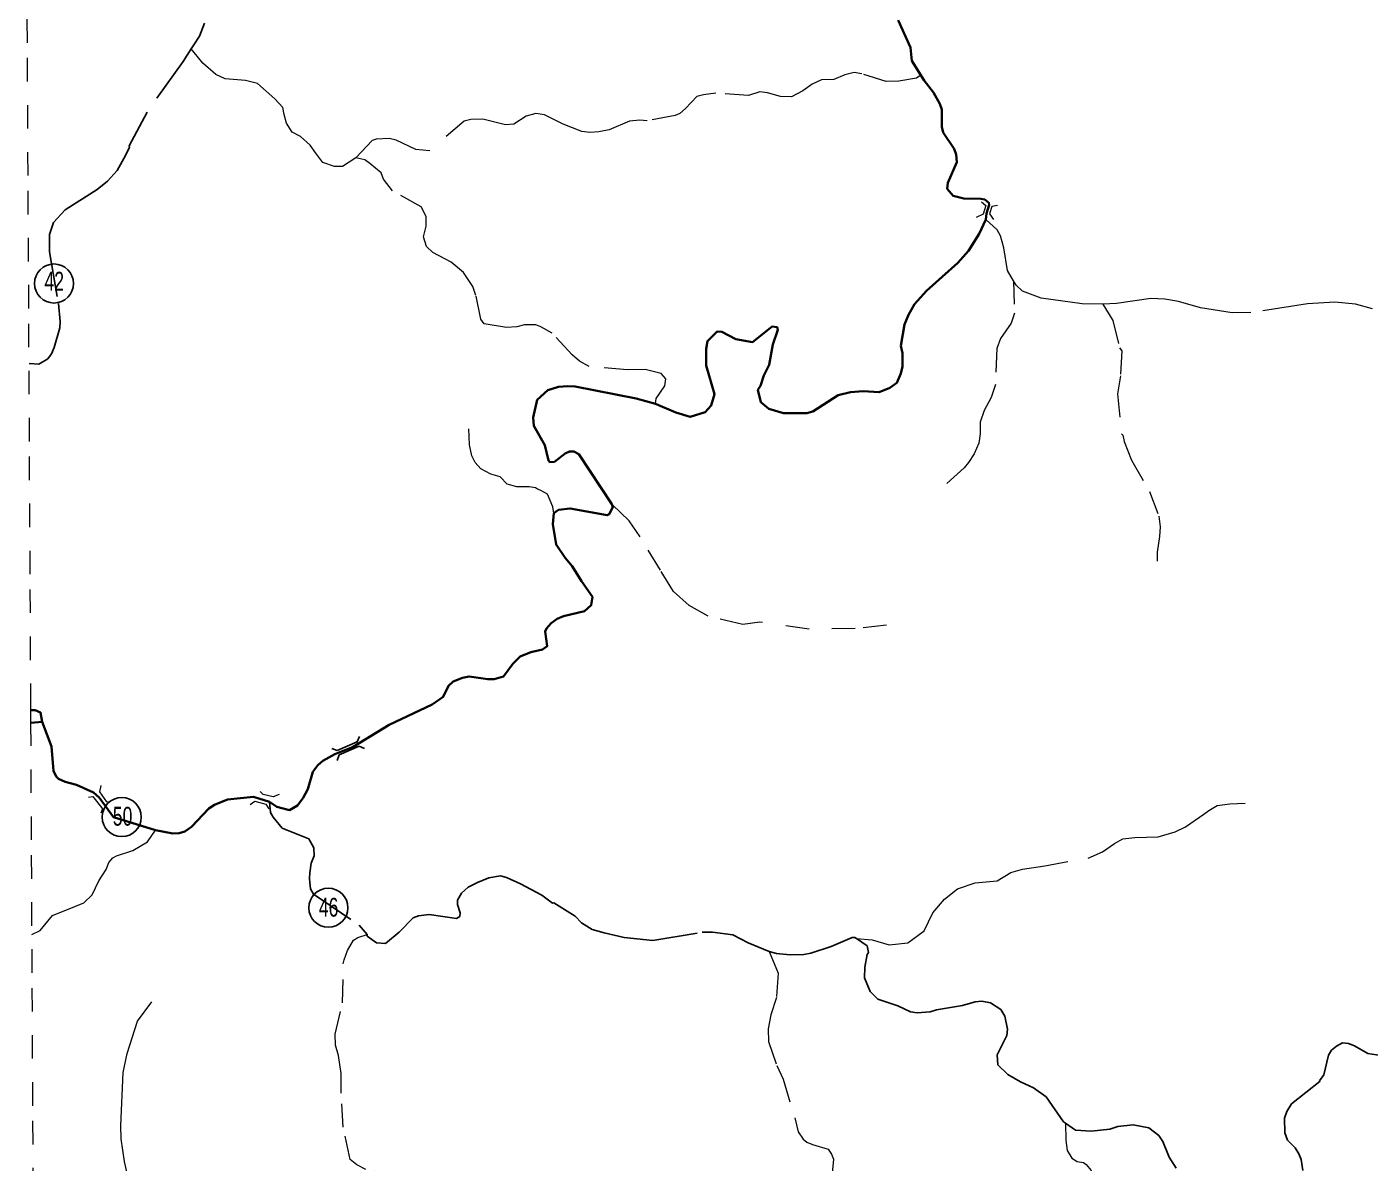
# Model space of a CAD drawing. Extents: x 423 to 448.8, y 7456.3 to 7484.
# Drawn here: x 423.01 to 428.72, y 7474.65 to 7479.48 of the extents above; entities that cross this region are included whole.
import ezdxf
from ezdxf.enums import TextEntityAlignment as Align

# ---------------------------------------------------------------- set-up
doc = ezdxf.new("R2010")
doc.units = 0
doc.header["$LTSCALE"] = 0.032
for name, pattern in [('LONG_DASHED', [7.5, 6, -1.5]), ('MEDIUM_DASHED', [4.5, 3, -1.5]), ('SHORT_DASHED', [2.7, 1.5, -1.2])]:
    doc.linetypes.add(name, pattern=pattern)
for name, color, linetype, lineweight in [('10', 7, 'Continuous', 25), ('11', 7, 'Continuous', 13), ('13', 7, 'Continuous', 25), ('2', 7, 'Continuous', 35), ('35', 7, 'SHORT_DASHED', 13), ('4', 7, 'LONG_DASHED', 25), ('5', 7, 'LONG_DASHED', 13), ('6', 7, 'MEDIUM_DASHED', 13), ('7', 7, 'Continuous', 13)]:
    doc.layers.add(name, color=color, linetype=linetype, lineweight=lineweight)
doc.layers.add('61', color=7, linetype='Continuous')

msp = doc.modelspace()

# ---------------------------------------------------------------- linework, layer by layer
at = {"layer": '10'}
for p, q in [((424.3335, 7476.3992), (424.3104, 7476.4085)), ((424.3325, 7476.3578), (424.3415, 7476.3809)), ((424.3415, 7476.3809), (424.4263, 7476.4179)), ((424.4495, 7476.4088), (424.4263, 7476.4179))]:
    msp.add_line(p, q, dxfattribs=at)
msp.add_lwpolyline([(424.3335, 7476.3992), (424.4183, 7476.4362), (424.4275, 7476.4595)], dxfattribs=at)
at = {"layer": '11'}
for p, q in [((423.3354, 7476.1516), (423.3285, 7476.133)), ((423.3529, 7476.1821), (423.3653, 7476.1832))]:
    msp.add_line(p, q, dxfattribs=at)
for points in [[(427.0732, 7478.7318), (427.0915, 7478.7163), (427.0793, 7478.6796), (427.0508, 7478.6652)], [(427.1402, 7478.7169), (427.1172, 7478.7118), (427.1064, 7478.6811), (427.1237, 7478.6576)], [(423.3279, 7476.2508), (423.322, 7476.2233), (423.3529, 7476.1821)], [(424.0863, 7476.2122), (424.0613, 7476.2023), (424.0185, 7476.2124), (424.0056, 7476.226)], [(423.2751, 7476.2006), (423.2941, 7476.204), (423.3354, 7476.1516)], [(423.9631, 7476.1703), (423.9835, 7476.1848), (424.0298, 7476.1715), (424.0424, 7476.1517)]]:
    msp.add_lwpolyline(points, dxfattribs=at)
at = {"layer": '13'}
for centre in [(423.129, 7478.3848), (423.4173, 7476.1165), (424.2956, 7475.731)]:
    msp.add_circle(centre, 0.083, dxfattribs=at)
at = {"layer": '2'}
msp.add_line((423.0308, 7476.517), (423.0792, 7476.5213), dxfattribs=at)
for points in [[(426.8144, 7479.2707), (426.7762, 7479.3321), (426.7706, 7479.388), (426.7191, 7479.5039)], [(426.1325, 7477.9503), (426.1222, 7477.9331), (426.135, 7477.8807), (426.1686, 7477.8523), (426.2304, 7477.8335), (426.3301, 7477.8343), (426.3558, 7477.8404), (426.464, 7477.9108), (426.5156, 7477.9228), (426.5703, 7477.9278), (426.6378, 7477.9236), (426.6831, 7477.9412), (426.7127, 7477.9625), (426.7303, 7478.0026), (426.7371, 7478.0327), (426.7371, 7478.0894), (426.7303, 7478.1195), (426.7461, 7478.2109), (426.7618, 7478.2519), (426.7886, 7478.2967), (426.8393, 7478.353), (426.9716, 7478.4724), (427.0171, 7478.524), (427.0635, 7478.5961), (427.0907, 7478.6576), (427.0935, 7478.682), (427.1056, 7478.7189), (427.1039, 7478.7284), (427.0867, 7478.7413), (427.0704, 7478.7447), (426.9982, 7478.7456), (426.9527, 7478.7576), (426.9273, 7478.7877), (426.9295, 7478.8126), (426.9673, 7478.901), (426.9647, 7478.9328), (426.957, 7478.9569), (426.9097, 7479.0273), (426.9046, 7479.0513), (426.9046, 7479.1252), (426.896, 7479.1492), (426.8694, 7479.1973), (426.8289, 7479.2473), (426.8144, 7479.2707)], [(423.0792, 7476.5213), (423.1188, 7476.4164), (423.1274, 7476.3133), (423.1386, 7476.2893), (423.148, 7476.279), (423.1764, 7476.2661), (423.2245, 7476.254), (423.2975, 7476.2214), (423.3215, 7476.2), (423.3814, 7476.116), (423.5611, 7476.0608), (423.635, 7476.0471), (423.6608, 7476.0479), (423.6848, 7476.0548), (423.7131, 7476.0754), (423.7879, 7476.1536), (423.8119, 7476.169), (423.8663, 7476.192), (423.9773, 7476.2027), (424.0449, 7476.1814), (424.0763, 7476.16), (424.1309, 7476.1461), (424.1642, 7476.1656), (424.1892, 7476.1985), (424.2077, 7476.2356), (424.2301, 7476.309), (424.2508, 7476.3374), (424.2723, 7476.3563), (424.3238, 7476.3837), (424.4011, 7476.4155), (424.554, 7476.5092), (424.737, 7476.5959), (424.7842, 7476.6283), (424.8064, 7476.674), (424.8262, 7476.6929), (424.8666, 7476.7092), (424.8941, 7476.7144), (424.9731, 7476.7024), (425.0006, 7476.7032), (425.0401, 7476.7136), (425.0804, 7476.7685), (425.1113, 7476.7986), (425.1569, 7476.8183), (425.2067, 7476.8295), (425.2264, 7476.8432), (425.2178, 7476.905), (425.223, 7476.9188), (425.2427, 7476.9403), (425.2685, 7476.9592), (425.296, 7476.9712), (425.3846, 7476.9923), (425.4132, 7477.0173), (425.4188, 7477.0528), (425.3716, 7477.1189), (425.3329, 7477.1833), (425.302, 7477.2185), (425.2641, 7477.2748), (425.2504, 7477.3611), (425.2547, 7477.4083), (425.2737, 7477.4221), (425.3235, 7477.4289), (425.4807, 7477.3997), (425.4901, 7477.4049), (425.5055, 7477.4341), (425.5004, 7477.447), (425.3604, 7477.6591), (425.3398, 7477.6711), (425.3209, 7477.6703), (425.302, 7477.6625), (425.2565, 7477.6265), (425.2376, 7477.6256), (425.2316, 7477.6325), (425.2161, 7477.6978), (425.1697, 7477.7793), (425.1671, 7477.8146), (425.1838, 7477.8901), (425.2292, 7477.9309), (425.2745, 7477.946), (425.3132, 7477.9486), (425.3447, 7477.9466), (425.6047, 7477.8954), (425.6861, 7477.874), (425.7731, 7477.8365), (425.8342, 7477.8179), (425.898, 7477.8383), (425.9239, 7477.8661), (425.9369, 7477.9148), (425.9027, 7478.0358), (425.9017, 7478.1068), (425.9082, 7478.1401), (425.9489, 7478.1809), (425.9693, 7478.179), (426.0285, 7478.148), (426.0997, 7478.136), (426.1821, 7478.2018), (426.2038, 7478.1993), (426.2072, 7478.1882), (426.1858, 7478.1255), (426.1702, 7478.0393), (426.1471, 7477.9941), (426.1325, 7477.9503)], [(423.0792, 7476.5213), (423.0719, 7476.5609), (423.0487, 7476.5711), (423.0306, 7476.5713)]]:
    msp.add_lwpolyline(points, dxfattribs=at)
at = {"layer": '35'}
for points in [[(423.0308, 7476.517), (423.0305, 7476.5843), (423.0276, 7477.1491), (423.0247, 7477.7139), (423.0219, 7478.2787), (423.019, 7478.8436), (423.0161, 7479.4084), (423.0136, 7479.9058)], [(423.0419, 7474.325), (423.0391, 7474.8898), (423.0362, 7475.4546), (423.0333, 7476.0195), (423.0308, 7476.517)]]:
    msp.add_lwpolyline(points, dxfattribs=at)
at = {"layer": '4'}
for points in [[(423.769, 7479.4911), (423.7475, 7479.4369), (423.7236, 7479.3995), (423.7127, 7479.3825), (423.6781, 7479.3284), (423.5251, 7479.1136), (423.4488, 7478.9694), (423.4495, 7478.9628), (423.4263, 7478.9156), (423.3971, 7478.8658), (423.3567, 7478.8194), (423.3121, 7478.7851), (423.1772, 7478.6983), (423.1274, 7478.6442), (423.1102, 7478.5927), (423.1094, 7478.5188), (423.1483, 7478.3004), (423.1558, 7478.2234), (423.154, 7478.1959), (423.1291, 7478.1135), (423.118, 7478.086), (423.1026, 7478.065), (423.0647, 7478.0425), (423.0231, 7478.0442)], [(424.0449, 7476.1814), (424.0499, 7476.1364), (424.0606, 7476.1157), (424.0992, 7476.0702), (424.2127, 7476.0239), (424.2345, 7475.986), (424.2359, 7475.9521), (424.2219, 7475.9201), (424.2166, 7475.8801), (424.2151, 7475.8567), (424.2163, 7475.8372), (424.2204, 7475.8112), (424.2326, 7475.7895), (424.4271, 7475.6578), (424.4601, 7475.6178), (424.4603, 7475.6108), (424.5007, 7475.5816), (424.5385, 7475.5799), (424.5969, 7475.628), (424.6561, 7475.6881), (424.6793, 7475.6975), (424.724, 7475.7027), (424.8401, 7475.685), (424.855, 7475.6943), (424.8559, 7475.7093), (424.8442, 7475.7456), (424.8442, 7475.7637), (424.8614, 7475.7929), (424.8906, 7475.8186), (424.9301, 7475.8384), (424.9782, 7475.859), (425.028, 7475.8667), (425.0538, 7475.8599), (425.1129, 7475.8333), (425.2036, 7475.7843), (425.2487, 7475.7511), (425.2547, 7475.7525), (425.3449, 7475.6955), (425.3716, 7475.6675), (425.4167, 7475.639), (425.4679, 7475.625), (425.5538, 7475.6041), (425.6749, 7475.5919), (425.8847, 7475.627), (425.9293, 7475.6279), (426.0154, 7475.6163), (426.0805, 7475.5818), (426.1693, 7475.5458), (426.2012, 7475.536), (426.2596, 7475.5309), (426.318, 7475.5326), (426.3472, 7475.5378), (426.4331, 7475.5661), (426.5232, 7475.6048), (426.5344, 7475.6048), (426.5418, 7475.5998), (426.5868, 7475.5696), (426.592, 7475.5403), (426.5868, 7475.5326), (426.577, 7475.478), (426.5756, 7475.4337), (426.5988, 7475.3755), (426.6323, 7475.3419), (426.7165, 7475.3145), (426.7715, 7475.2887), (426.799, 7475.2844), (426.8539, 7475.2887), (426.8814, 7475.2973), (426.9914, 7475.3154), (427.0463, 7475.3317), (427.0738, 7475.3334), (427.1107, 7475.3274), (427.1554, 7475.2982), (427.1717, 7475.2707), (427.1829, 7475.2157), (427.1811, 7475.1883), (427.1399, 7475.1058), (427.1416, 7475.0637), (427.1846, 7475.0225), (427.2387, 7474.9907), (427.2937, 7474.9658), (427.3477, 7474.928), (427.4216, 7474.8215), (427.4307, 7474.8153), (427.4731, 7474.7863), (427.5396, 7474.7811), (427.6183, 7474.7897), (427.6527, 7474.8009), (427.7171, 7474.8081), (427.7838, 7474.796), (427.827, 7474.7631), (427.8433, 7474.7382), (427.8708, 7474.6712), (427.9008, 7474.6248)], [(428.4385, 7474.6146), (428.4316, 7474.6609), (428.4222, 7474.685), (428.4059, 7474.7099), (428.3741, 7474.7425), (428.3621, 7474.7743), (428.3612, 7474.8361), (428.3706, 7474.8653), (428.3912, 7474.8971), (428.5132, 7474.9941), (428.5106, 7474.9959), (428.5278, 7475.0216), (428.5476, 7475.1041), (428.5604, 7475.1264), (428.5819, 7475.1427), (428.6077, 7475.1565), (428.6335, 7475.1539), (428.6592, 7475.1444), (428.7159, 7475.1118), (428.7709, 7475.1024)]]:
    msp.add_lwpolyline(points, dxfattribs=at)
at = {"layer": '5'}
msp.add_lwpolyline([(428.7348, 7478.2766), (428.6627, 7478.2973), (428.5751, 7478.305), (428.4583, 7478.2981), (428.2179, 7478.2615), (428.1388, 7478.2595), (428.0039, 7478.2809), (427.9103, 7478.3084), (427.8519, 7478.3187), (427.7935, 7478.3213), (427.6475, 7478.2998), (427.5884, 7478.2975), (427.5015, 7478.2981), (427.3263, 7478.323), (427.2473, 7478.3522), (427.2198, 7478.3771), (427.2086, 7478.3963), (427.1828, 7478.4407), (427.1683, 7478.536), (427.1536, 7478.5876), (427.1399, 7478.6133), (427.0907, 7478.6576)], dxfattribs=at)
at = {"layer": '6'}
for points in [[(424.4122, 7478.9185), (424.3559, 7478.8823), (424.3224, 7478.8818), (424.2723, 7478.8996), (424.242, 7478.9394), (424.2176, 7478.9723), (424.1778, 7479.0092), (424.142, 7479.0281), (424.1176, 7479.066), (424.1082, 7479.1028), (424.1022, 7479.1329), (424.0687, 7479.1698), (423.9943, 7479.2349), (423.9435, 7479.2478), (423.8574, 7479.2548), (423.817, 7479.2738), (423.7612, 7479.3218), (423.738, 7479.3519), (423.7127, 7479.3825)], [(426.8144, 7479.2707), (426.7965, 7479.2582), (426.722, 7479.2447), (426.6681, 7479.2432), (426.5637, 7479.2763), (426.5318, 7479.2815), (426.4915, 7479.272), (426.4451, 7479.2523), (426.3927, 7479.2506), (426.3532, 7479.2325), (426.3129, 7479.2033), (426.2656, 7479.1784), (426.2184, 7479.1793), (426.1634, 7479.1956), (426.1299, 7479.1991), (426.0827, 7479.1835), (425.9436, 7479.1937), (425.8903, 7479.187), (425.8619, 7479.1793), (425.8147, 7479.1286), (425.7907, 7479.108), (425.7701, 7479.0986), (425.6516, 7479.0762), (425.6206, 7479.0797), (425.5768, 7479.0745), (425.4892, 7479.0384), (425.4454, 7479.029), (425.4077, 7479.0264), (425.3733, 7479.0307), (425.2934, 7479.0616), (425.2144, 7479.102), (425.1783, 7479.1071), (425.1371, 7479.0968), (425.0838, 7479.0625), (425.0487, 7479.0591), (424.9525, 7479.0831), (424.9009, 7479.0822), (424.8725, 7479.0749), (424.7277, 7478.9484), (424.6673, 7478.9551), (424.5841, 7478.9939), (424.554, 7479.0007), (424.499, 7478.9989), (424.4826, 7478.9929), (424.4122, 7478.9185)], [(425.6861, 7477.874), (425.6889, 7477.8956), (425.7262, 7477.9504), (425.7312, 7477.9803), (425.7113, 7478.0022), (425.643, 7478.0198), (425.5674, 7478.0181), (425.4042, 7478.0319), (425.3629, 7478.055), (425.3329, 7478.0817), (425.247, 7478.1744), (425.1989, 7478.2002), (425.1775, 7478.2088), (425.1302, 7478.2097), (425.0968, 7478.201), (425.0538, 7478.1985), (424.9585, 7478.214), (424.9438, 7478.2328), (424.9232, 7478.3333), (424.9095, 7478.3728), (424.8709, 7478.4321), (424.8176, 7478.475), (424.7403, 7478.5163), (424.7128, 7478.542), (424.7, 7478.5832), (424.7111, 7478.6288), (424.7119, 7478.67), (424.6905, 7478.7103), (424.5685, 7478.779), (424.5299, 7478.8289), (424.5203, 7478.8547), (424.4727, 7478.8955), (424.4502, 7478.9106), (424.4122, 7478.9185)], [(427.2086, 7478.3963), (427.2137, 7478.2582), (427.1992, 7478.2165), (427.1536, 7478.1504), (427.1382, 7478.1083), (427.1322, 7477.9554), (427.1141, 7477.8996), (427.0841, 7477.8455), (427.0678, 7477.7948), (427.0678, 7477.7459), (427.0617, 7477.7064), (427.0412, 7477.6608), (427.018, 7477.6239), (426.9991, 7477.6016), (426.9089, 7477.52)], [(427.5884, 7478.2975), (427.6313, 7478.2271), (427.6601, 7478.1116), (427.6698, 7478.0988), (427.6634, 7477.993), (427.6505, 7477.916), (427.6681, 7477.7465), (427.6741, 7477.7399), (427.6793, 7477.7133), (427.711, 7477.6342), (427.7866, 7477.5011), (427.8262, 7477.3963), (427.8322, 7477.3508), (427.8304, 7477.3096), (427.8193, 7477.243), (427.8203, 7477.2051)], [(425.2547, 7477.4083), (425.2505, 7477.4351), (425.2271, 7477.4891), (425.1964, 7477.5067), (425.1855, 7477.5099), (425.1766, 7477.5163), (425.1495, 7477.5208), (425.0971, 7477.5203), (425.0559, 7477.5321), (425.0256, 7477.5633), (424.9871, 7477.575), (424.9437, 7477.5975), (424.92, 7477.6246), (424.9061, 7477.6519), (424.8957, 7477.6996), (424.8931, 7477.7665)], [(426.6684, 7476.9323), (426.5361, 7476.9182), (426.3397, 7476.916), (426.1303, 7476.9453), (426.0586, 7476.9353), (425.9107, 7476.9707), (425.83, 7477.0158), (425.7635, 7477.0759), (425.7079, 7477.166), (425.6208, 7477.308), (425.5747, 7477.3754), (425.5004, 7477.447)], [(426.5418, 7475.5998), (426.608, 7475.5944), (426.6802, 7475.5739), (426.7596, 7475.5824), (426.8288, 7475.6325), (426.8661, 7475.7097), (426.916, 7475.7682), (426.9714, 7475.8116), (427.0466, 7475.8364), (427.1393, 7475.846), (427.1976, 7475.8813), (427.247, 7475.8949), (427.342, 7475.9096), (427.5268, 7475.9426), (427.587, 7475.9691), (427.6388, 7476.004), (427.6744, 7476.0239), (427.7253, 7476.0305), (427.8235, 7476.0324), (427.8962, 7476.0541), (427.9396, 7476.0749), (428.018, 7476.1296), (428.0395, 7476.1439), (428.0756, 7476.1665), (428.1292, 7476.1735), (428.1941, 7476.1759)], [(424.7156, 7474.5244), (424.59, 7474.5887), (424.4543, 7474.6179), (424.4165, 7474.6377), (424.3882, 7474.6617), (424.359, 7474.7983), (424.3495, 7474.9426), (424.3504, 7475.0268), (424.3384, 7475.1024), (424.3255, 7475.147), (424.3246, 7475.1934), (424.3564, 7475.3265), (424.359, 7475.4923), (424.3633, 7475.5095), (424.377, 7475.5498), (424.4028, 7475.5928), (424.4208, 7475.6048), (424.4601, 7475.6178)], [(426.1693, 7475.5458), (426.2081, 7475.4536), (426.2015, 7475.3497), (426.1775, 7475.2764), (426.1651, 7475.2168), (426.1667, 7475.1626), (426.2026, 7475.0613), (426.2289, 7475.0022), (426.2792, 7474.8386), (426.2934, 7474.779), (426.314, 7474.7474), (426.3301, 7474.735), (426.3548, 7474.7249), (426.4203, 7474.7048), (426.435, 7474.6841), (426.4442, 7474.6626), (426.4374, 7474.6016)]]:
    msp.add_lwpolyline(points, dxfattribs=at)
at = {"layer": '7'}
for points in [[(423.0354, 7475.6169), (423.0708, 7475.6344), (423.1224, 7475.6978), (423.2172, 7475.736), (423.2554, 7475.7519), (423.2916, 7475.7855), (423.3194, 7475.8458), (423.3504, 7475.894), (423.3617, 7475.9242), (423.3791, 7475.9434), (423.3946, 7475.9515), (423.4643, 7475.9739), (423.5271, 7476.0112), (423.5611, 7476.0608)], [(423.0443, 7473.8655), (423.0534, 7473.8655), (423.1078, 7473.8448), (423.1459, 7473.8601), (423.1665, 7473.8862), (423.1774, 7473.958), (423.1894, 7473.9852), (423.2119, 7474.0036), (423.3232, 7474.0941), (423.3406, 7474.1157), (423.3939, 7474.1735), (423.4222, 7474.2225), (423.4581, 7474.2998), (423.469, 7474.4728), (423.4283, 7474.652), (423.4142, 7474.7488), (423.4133, 7474.8042), (423.4236, 7475.0315), (423.4396, 7475.1114), (423.4837, 7475.2485), (423.5445, 7475.3309)], [(427.4307, 7474.8153), (427.4319, 7474.7419), (427.4365, 7474.6988), (427.4574, 7474.6668), (427.4798, 7474.6527), (427.5061, 7474.6479), (427.5176, 7474.6392), (427.5393, 7474.6148), (427.5609, 7474.5551), (427.5758, 7474.4562), (427.5781, 7474.3897), (427.5688, 7474.2293)]]:
    msp.add_lwpolyline(points, dxfattribs=at)

# ---------------------------------------------------------------- texts
at = {"layer": '61', "width": 0.7}
for s, p in [('42', (423.13, 7478.3547)), ('50', (423.4207, 7476.0802)), ('46', (424.2966, 7475.6935))]:
    msp.add_text(s, height=0.08, dxfattribs=at).set_placement(p, align=Align.CENTER)

doc.saveas('drawing.dxf')
